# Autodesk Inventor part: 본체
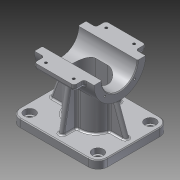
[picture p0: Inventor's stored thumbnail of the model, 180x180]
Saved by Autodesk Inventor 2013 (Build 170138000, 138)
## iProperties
Company: 한국ATC센터
Created: 2014-02
Part Number: 본체
Document SubType Name: Modeling
Designer: KYOUNG IL JANG
Density: 2.71 g/cm^3
Material: 알루미늄-6061
Vendor: CBT Solutions
Mass: 556.917 g
Surface Area: 547.39 cm^2
Volume: 205.505 cm^3
Author: KYOUNG IL JANG
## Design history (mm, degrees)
sketch "스케치1"
  geometry: L1 (-55, 45)-(55, 45); L2 (55, 45)-(55, -45); L3 (55, -45)-(-55, -45); L4 (-55, -45)-(-55, 45); 3 further points
  constraints: 8 end point, 2 midpoint, 2 parallel, 1 horizontal, 1 horizontal alignment, 1 perpendicular, 1 vertical alignment
  dimensions: "d0" = 110 distance of L2.end L3.end; "d1" = 90 distance of L1.end L2.end
extrude "돌출1" new body sketch "스케치1" distance "d2" = 10; taper "d3" = 0 deg
sketch "스케치2"
  geometry: L1 (45, 0)-(-45, 0) reference; C1 r 32.5 at (0, 80); 2 further points
  constraints: 1 centre point, 1 midpoint, 1 vertical alignment
  dimensions: "d4" = 65 diameter of C1; "d5" = 80 distance from line of C1.centre L1
extrude "돌출2" join sketch "스케치2" stored distance "d6" = 75; taper "d7" = 0 deg
sketch "스케치3"
  geometry: L1 (-7.5, -20)-(7.5, -20); L2 (7.5, 20)-(-7.5, 20); A1 r 20 centre (7.5, 0) between (7.5, -20) and (7.5, 20); A2 r 20 centre (-7.5, 0) between (-7.5, 20) and (-7.5, -20); 2 further points
  constraints: 4 end point, 4 point on circle, 4 tangent, 2 centre point, 1 horizontal, 1 horizontal alignment, 1 midpoint, 1 parallel, 1 vertical alignment
  dimensions: "d8" = 20 radius of A2; "d9" = 55 dimension on A1 A2
extrude "돌출3" join sketch "스케치3" stored distance "d10" = 75; taper "d11" = 0 deg
fillet "모깎기1" dims "d12" = 12
sketch "스케치4"
  geometry: L1 (-55, 0)-(-55, 10) reference; L2 (37.5, 47.5)-(-37.5, 47.5) reference; L3 (-48, 10)-(-34.351, 47.5); 1 further point
  constraints: 2 end point, 1 horizontal alignment, 1 point on line
  dimensions: "d105" = 7 distance from line of L3.start L1; "d106" = 110 deg dimension on L3.start L3.end L1.end
sketch "스케치5"
  geometry: L1 (-45, 0)-(-45, 10) reference; L2 (-38, 10)-(-28.433, 64.258); 2 further points
  constraints: 2 end point, 1 horizontal alignment, 2 other
  dimensions: "d107" = 7 distance from line of L2.start L1; "d108" = 100 deg dimension on L2.start L2.end L1.end
feature "리브1" dims "d15" = 1, "d16" = 6, "d17" = 0
feature "리브2" dims "d18" = 1, "d19" = 6, "d20" = 0
fillet "모깎기3" dims "d22" = 3
fillet "모깎기4" dims "d23" = 3
fillet "모깎기5" dims "d24" = 3
fillet "모깎기6" dims "d25" = 3
fillet "모깎기7" dims "d26" = 3
fillet "모깎기12" dims "d109" = 2
sketch "스케치6"
  geometry: A1 r 12 centre (43, -33) between (43, -45) and (55, -33) reference; A2 r 12 centre (-43, -33) between (-55, -33) and (-43, -45) reference; A3 r 12 centre (-43, 33) between (-43, 45) and (-55, 33) reference; A4 r 12 centre (43, 33) between (55, 33) and (43, 45) reference; 1 further point
hole "구멍7" sketch "스케치6" at (43, -33), (-43, -33), (-43, 33), (43, 33) diameter "d110" = 9; stored, may be unused: countersink angle "d114" = 90 deg, drill point angle "d116" = 118 deg; dims "d111" = 6, "d112" = 14, "d113" = 6.6, "d115" = 8
hole "구멍2" diameter "d37" = 45; stored, may be unused: countersink angle "d41" = 90 deg, drill point angle "d43" = 118 deg; dims "d35" = 10, "d36" = 10, "d38" = 6, "d39" = 4, "d40" = 2, "d42" = 8
sketch "스케치7"
  geometry: C1 r 22.5 at (0, 0) reference; 2 further points
  dimensions: "d44" = 135 deg dimension on C1.centre point (-18.738, 18.738) point (80, 0); "d45" = 26.5 distance of point (-18.738, 18.738) C1.centre
hole "구멍3" sketch "스케치7" at (-18.738, 18.738) diameter "d46" = 2.459; stored, may be unused: countersink angle "d50" = 90 deg, drill point angle "d52" = 118 deg; dims "d47" = 8, "d48" = 4, "d49" = 2, "d51" = 10
node "작업 평면1"
sketch "스케치8"
  geometry: C1 r 10 at (0, 0); 1 further point
  constraints: 1 centre point, 1 coincident
  dimensions: "d57" = 20 diameter of C1
extrude "돌출4" join sketch "스케치8" stored distance "d58" = 75; taper "d59" = 0 deg
hole "구멍4" diameter "d62" = 8.376; stored, may be unused: countersink angle "d66" = 90 deg, drill point angle "d68" = 118 deg; dims "d60" = 10, "d61" = 10, "d63" = 7, "d64" = 4, "d65" = 2, "d67" = 10
chamfer "모따기1" distance "d69" = 1; stored, may be unused: second distance "d70" = 2, angle "d71" = 45 deg
fillet "모깎기9" dims "d72" = 3
sketch "스케치9"
  geometry: L1 (-31.623, 87.5)-(-45, 87.5); L2 (-45, 87.5)-(-45, 72.5); L3 (-45, 72.5)-(-31.623, 72.5); A1 r 32.5 centre (0, 80) between (-31.623, 87.5) and (-31.623, 72.5) reference; 1 further point
  constraints: 6 end point, 2 parallel, 2 point on circle, 1 horizontal, 1 perpendicular
  dimensions: "d73" = 15 distance of L1.end L2.end; "d74" = 45 distance from line of A1.centre L2
extrude "돌출5" join sketch "스케치9" stored distance "d75" = 50; taper "d76" = 0 deg
fillet "모깎기10" dims "d77" = 3
fillet "모깎기11" dims "d78" = 3
sketch "스케치10"
  geometry: L1 (-61.625, 62.366)-(0, 62.366); L2 (0, 62.366)-(0, -62.366); L3 (0, -62.366)-(-61.625, -62.366); L4 (-61.625, -62.366)-(-61.625, 62.366); C1 r 32.5 at (0, 0) reference; 2 further points
  constraints: 8 end point, 2 parallel, 1 coincident, 1 horizontal, 1 midpoint, 1 perpendicular
extrude "돌출6" cut sketch "스케치10" stored distance "d79" = 10; taper "d80" = 0 deg
node "작업 평면2"
sketch "스케치11"
  geometry: L1 (-7.5, -15)-(7.5, -15); L2 (7.5, 15)-(-7.5, 15); A1 r 15 centre (7.5, 0) between (7.5, -15) and (7.5, 15); A2 r 15 centre (-7.5, 0) between (-7.5, 15) and (-7.5, -15); 2 further points
  constraints: 4 end point, 4 point on circle, 4 tangent, 2 centre point, 1 horizontal, 1 horizontal alignment, 1 midpoint, 1 parallel, 1 vertical alignment
  dimensions: "d82" = 15 radius of A2; "d117" = 45 dimension on A2 A1
extrude "돌출7" cut sketch "스케치11" stored distance "d83" = 10; taper "d84" = 0 deg
sketch "스케치12"
  geometry: 1 further point
hole "구멍5" sketch "스케치12" at (0, 0) diameter "d85" = 12; stored, may be unused: countersink angle "d89" = 90 deg, drill point angle "d91" = 118 deg; dims "d86" = 6, "d87" = 38, "d88" = 10, "d90" = 8
sketch "스케치13"
  geometry: L1 (-15.5, -12.5)-(-59.5, -12.5) reference; 3 further points
  constraints: 1 horizontal alignment
  dimensions: "d92" = 35 distance of point (-20, -5.5) point (-55, -5.5); "d93" = 17.5 horizontal distance of point (-37.5, 32.5) point (-55, -5.5) (= 0.5 x d92); "d94" = 7 distance from line of L1 point (-55, -5.5)
hole "구멍6" sketch "스케치13" at (-55, -5.5), (-20, -5.5) diameter "d95" = 3.242; stored, may be unused: countersink angle "d99" = 90 deg, drill point angle "d101" = 118 deg; dims "d96" = 6, "d97" = 38, "d98" = 10, "d100" = 8
sketch "스케치14"
  geometry: C1 r 10 at (0, 0); 1 further point
  constraints: 1 centre point, 1 coincident
  dimensions: "d102" = 20 diameter of C1
extrude "돌출8" cut sketch "스케치14" distance "d103" = 5; taper "d104" = 0 deg
chamfer "모따기2" distance "d118" = 1; stored, may be unused: second distance "d119" = 2, angle "d120" = 45 deg
node "솔리드1"
mirror "대칭1"
mirror "대칭2"
pattern_circular "원형 패턴1" dims angle "d54" = 360 deg
mirror "대칭5"
mirror "대칭6"
mirror "대칭7"
other parameters: "d56" = -117
